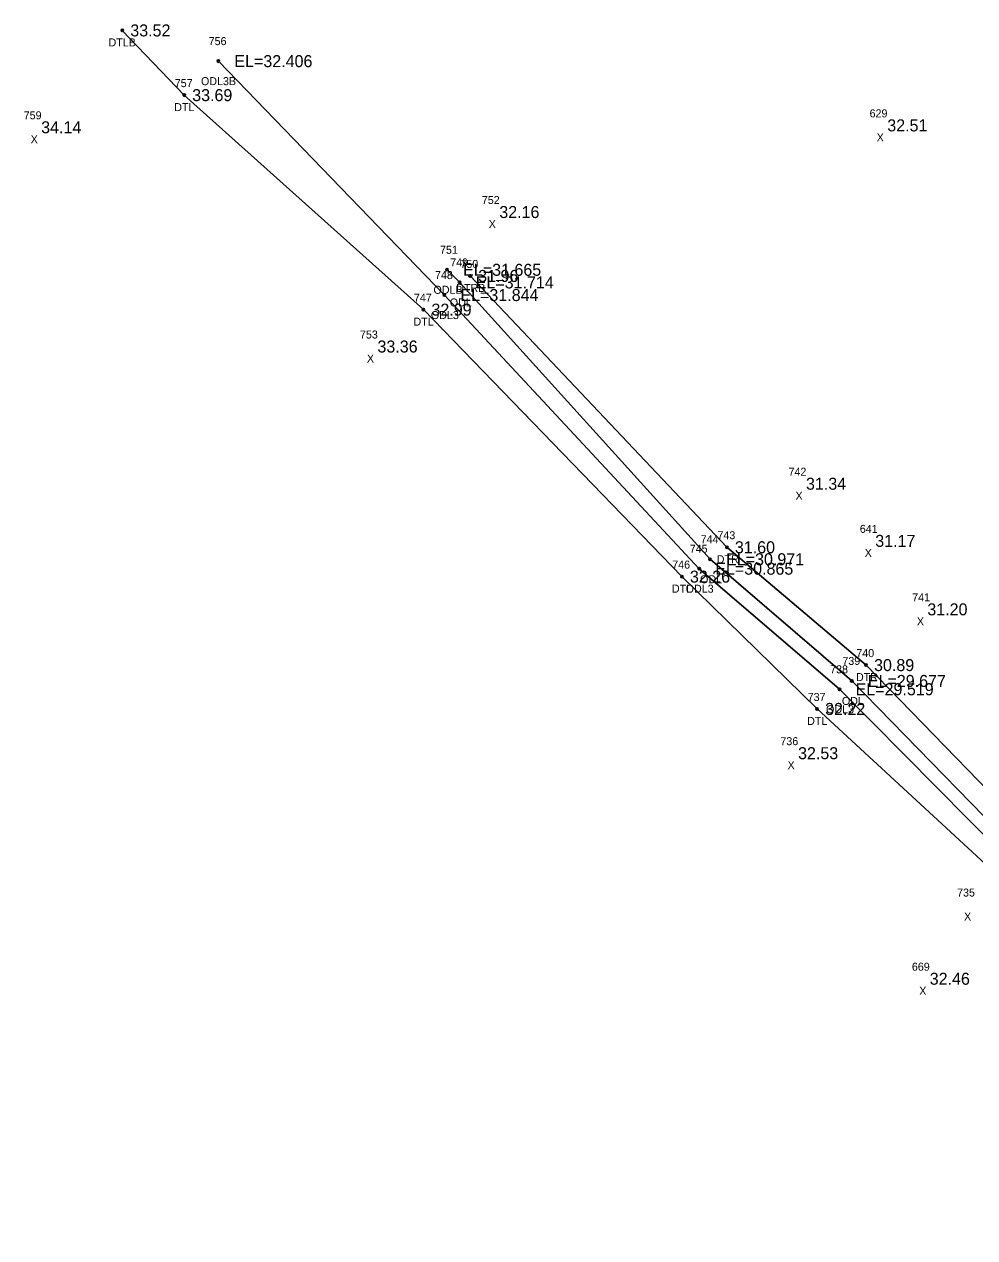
# Model space of a CAD drawing. Extents: x 2042117 to 2045853, y 303080 to 309569.
# Drawn here: x 2042632.8 to 2042751.6, y 307137.5 to 307289.2 of the extents above; entities that cross this region are included whole.
import ezdxf

# ---------------------------------------------------------------- set-up
doc = ezdxf.new("R2010")
doc.units = 0
for name, color, linetype in [('RD_EX_H2O', 7, 'Continuous'), ('RD_EX_H2O_txCode', 7, 'Continuous'), ('RD_EX_Misc_txCode', 7, 'Continuous'), ('RD_EX_TX_H2O_ELEV', 7, 'Continuous'), ('RD_EX_TX_Misc_ELEV', 7, 'Continuous'), ('RD_SMD_Locator', 7, 'Continuous')]:
    doc.layers.add(name, color=color, linetype=linetype)

msp = doc.modelspace()

# ---------------------------------------------------------------- linework, layer by layer
at = {"layer": 'RD_EX_H2O'}
for points in [[(2042814.03, 307149.05), (2042810.11, 307144.21), (2042802.02, 307139.29), (2042796.62, 307137.52), (2042789.54, 307144.39), (2042765.07, 307170.22), (2042764.17, 307170.66), (2042753.47, 307183.77), (2042731.92, 307203.61), (2042715.02, 307220.15), (2042682.71, 307253.52), (2042652.8, 307280.33), (2042645.06, 307288.42)], [(2042798.16, 307141.44), (2042792.07, 307147.01), (2042768.02, 307170.67), (2042763.43, 307175.3), (2042754.91, 307185.67), (2042734.73, 307206.07), (2042717.18, 307221.14), (2042685.33, 307255.34), (2042657.07, 307284.58)], [(2042770.54, 307208.78), (2042766.1, 307195.78), (2042762.33, 307183.06), (2042760.57, 307181.39), (2042756.11, 307186.78), (2042736.26, 307207.11), (2042718.54, 307222.32), (2042687.24, 307256.92), (2042685.67, 307258.5)], [(2042814.03, 307149.05), (2042812.35, 307160.17), (2042807.99, 307165.58), (2042796.92, 307172.8), (2042790.51, 307171.69), (2042792.71, 307164.76), (2042799.25, 307156.93), (2042800.45, 307151.16), (2042798.47, 307149.32), (2042796.14, 307150.22), (2042774.77, 307172.67), (2042769.03, 307177.06), (2042766.93, 307183.71), (2042770.19, 307195.04), (2042774.13, 307209.86), (2042772.99, 307212.66), (2042769.77, 307209.88), (2042763.43, 307196.28), (2042761.19, 307187.09), (2042759.15, 307187.36), (2042738.04, 307209.09), (2042720.64, 307223.82), (2042688.55, 307257.73)]]:
    msp.add_lwpolyline(points, dxfattribs=at)
at = {"layer": 'RD_SMD_Locator'}
for centre in [(2042645.06, 307288.42), (2042657.07, 307284.58), (2042652.8, 307280.33), (2042685.67, 307258.5), (2042688.55, 307257.73), (2042687.24, 307256.92), (2042685.33, 307255.34), (2042682.71, 307253.52), (2042720.64, 307223.82), (2042717.18, 307221.14), (2042718.54, 307222.32), (2042715.02, 307220.15), (2042738.04, 307209.09), (2042734.73, 307206.07), (2042736.26, 307207.11), (2042731.92, 307203.61)]:
    msp.add_circle(centre, 0.15, dxfattribs=at)

# ---------------------------------------------------------------- texts
at = {"layer": 'RD_EX_H2O_txCode'}
for s, p in [('DTLB', (2042643.34, 307286.42)), ('756', (2042655.86, 307286.58)), ('757', (2042651.62, 307281.33)), ('ODL3B', (2042654.9, 307281.58)), ('DTL', (2042651.56, 307278.33)), ('751', (2042684.78, 307260.5)), ('749', (2042686.06, 307258.92)), ('750', (2042687.33, 307258.73)), ('748', (2042684.15, 307257.34)), ('ODLB', (2042683.96, 307255.5)), ('DTRB', (2042686.81, 307255.73)), ('747', (2042681.52, 307254.52)), ('ODL', (2042686, 307253.92)), ('ODL3', (2042683.64, 307252.34)), ('DTL', (2042681.46, 307251.52)), ('743', (2042719.46, 307224.82)), ('744', (2042717.36, 307224.32)), ('745', (2042716, 307223.14)), ('DTR', (2042719.37, 307221.82)), ('746', (2042713.81, 307221.15)), ('ODL', (2042717.29, 307219.32)), ('DTL', (2042713.77, 307218.15)), ('ODL3', (2042715.49, 307218.14)), ('740', (2042736.82, 307210.09)), ('738', (2042733.55, 307208.07)), ('739', (2042735.08, 307209.11)), ('DTR', (2042736.78, 307207.09)), ('737', (2042730.74, 307204.61)), ('ODL', (2042735.02, 307204.11)), ('ODL3', (2042733.04, 307203.07)), ('DTL', (2042730.67, 307201.61))]:
    msp.add_text(s, height=1, dxfattribs=at).set_placement(p)
at = {"layer": 'RD_EX_Misc_txCode'}
for s, p in [('759', (2042632.74, 307277.31)), ('629', (2042738.48, 307277.55)), ('X', (2042633.61, 307274.31)), ('X', (2042739.37, 307274.55)), ('752', (2042690.01, 307266.72)), ('X', (2042690.87, 307263.72)), ('753', (2042674.77, 307249.91)), ('X', (2042675.64, 307246.91)), ('742', (2042728.35, 307232.76)), ('X', (2042729.22, 307229.76)), ('641', (2042737.26, 307225.62)), ('X', (2042737.87, 307222.62)), ('741', (2042743.81, 307217.06)), ('X', (2042744.39, 307214.06)), ('736', (2042727.33, 307199.08)), ('X', (2042728.22, 307196.08)), ('735', (2042749.42, 307180.16)), ('X', (2042750.29, 307177.16)), ('669', (2042743.77, 307170.89)), ('X', (2042744.69, 307167.89))]:
    msp.add_text(s, height=1, dxfattribs=at).set_placement(p)
at = {"layer": 'RD_EX_TX_H2O_ELEV'}
for s, p in [('33.52', (2042646.06, 307287.67)), ('EL=32.406', (2042659.07, 307283.83)), ('33.69', (2042653.8, 307279.58)), ('EL=31.665', (2042687.67, 307257.75)), ('EL=31.714', (2042689.24, 307256.17)), ('31.96', (2042689.55, 307256.98)), ('EL=31.844', (2042687.33, 307254.59)), ('32.99', (2042683.71, 307252.77)), ('31.60', (2042721.64, 307223.07)), ('EL=30.971', (2042720.54, 307221.57)), ('EL=30.865', (2042719.18, 307220.39)), ('32.26', (2042716.02, 307219.4)), ('30.89', (2042739.04, 307208.34)), ('EL=29.677', (2042738.26, 307206.36)), ('EL=29.519', (2042736.73, 307205.32)), ('32.22', (2042732.92, 307202.86))]:
    msp.add_text(s, height=1.5, dxfattribs=at).set_placement(p)
at = {"layer": 'RD_EX_TX_Misc_ELEV'}
for s, p in [('32.51', (2042740.69, 307275.8)), ('34.14', (2042634.92, 307275.56)), ('32.16', (2042692.19, 307264.97)), ('33.36', (2042676.96, 307248.16)), ('31.34', (2042730.53, 307231.01)), ('31.17', (2042739.19, 307223.87)), ('31.20', (2042745.7, 307215.31)), ('32.53', (2042729.54, 307197.33)), ('32.46', (2042746, 307169.14))]:
    msp.add_text(s, height=1.5, dxfattribs=at).set_placement(p)

doc.saveas('drawing.dxf')
